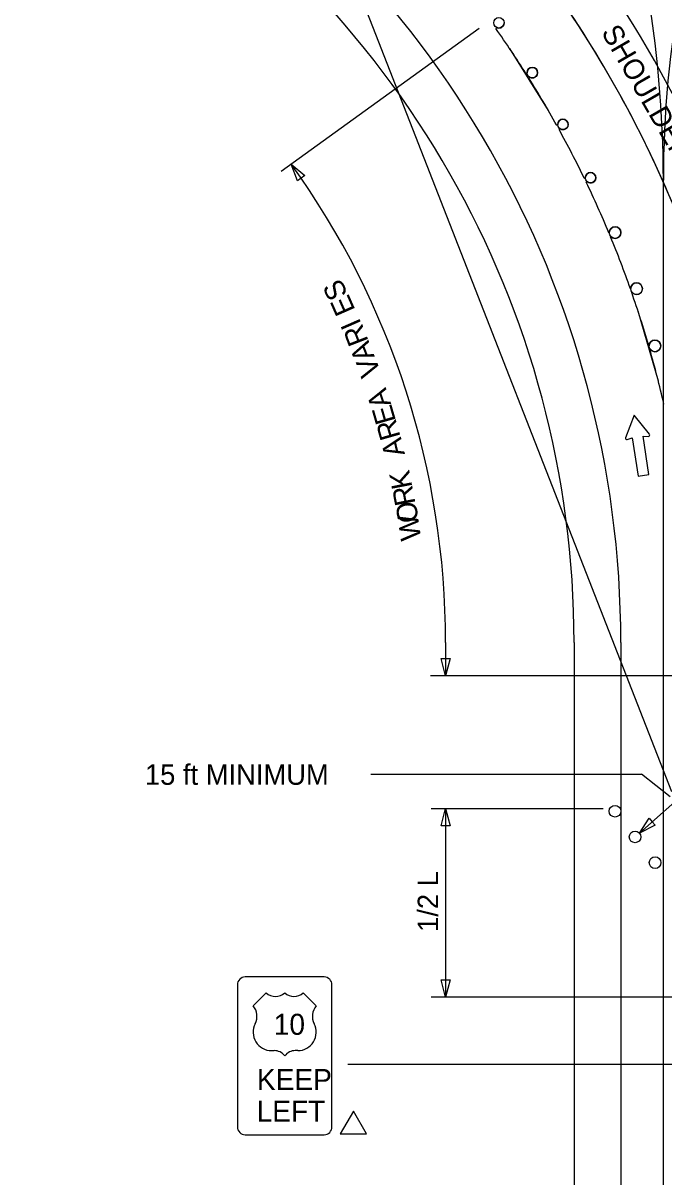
# Model space of a CAD drawing. Extents: x 16715 to 19504, y 7040 to 8495.
# Drawn here: x 16714.6 to 16934, y 7602.5 to 7997.5 of the extents above; entities that cross this region are included whole.
import ezdxf

# ---------------------------------------------------------------- set-up
doc = ezdxf.new("R2010")
doc.units = 0
for name, color, linetype in [('ALI_LEGAL_EX', 7, 'Continuous'), ('MT_SCRATCH_LEVEL_A', 7, 'Continuous'), ('MT_SCRATCH_LEVEL_E', 7, 'Continuous'), ('PAVT_EDGE_EX', 7, 'Continuous'), ('TRAFFIC_SIGNS_PR', 7, 'Continuous'), ('TYPICAL_EX', 7, 'Continuous'), ('TYPICAL_TEXT_DIMEN_PR', 7, 'Continuous')]:
    doc.layers.add(name, color=color, linetype=linetype)

msp = doc.modelspace()

# ---------------------------------------------------------------- linework, layer by layer
at = {"layer": 'ALI_LEGAL_EX'}
for p, q in [((16714.57, 8302.79), (16936.6, 7734.43)), ((16933.79, 7333.59), (16933.79, 7943.78)), ((16933.79, 7333.59), (16933.79, 7943.78))]:
    msp.add_line(p, q, dxfattribs=at)
for points in [[(16894.42, 7967.59), (16881.19, 7988.8)], [(16932.16, 7874.89), (16925.15, 7898.89)]]:
    msp.add_lwpolyline(points, dxfattribs=at)
for centre, radius, start, end in [((16545.79, 7943.78), 388, 0, 40.1908), ((17297.79, 7943.78), 364, 137.516, 180)]:
    msp.add_arc(centre, radius, start, end, dxfattribs=at)
at = {"layer": 'MT_SCRATCH_LEVEL_A'}
for points in [[(16876.9, 7995.96), (16876.46, 7995.65)], [(16886.74, 7980.31), (16887.14, 7980.57)], [(16888.15, 7978.95), (16887.75, 7978.69)], [(16897.24, 7962.65), (16897.61, 7962.86)], [(16898.45, 7961.34), (16898.08, 7961.14)], [(16906.72, 7944.43), (16907.06, 7944.6)], [(16907.74, 7943.19), (16907.4, 7943.03)], [(16915.14, 7925.77), (16915.28, 7925.83)], [(16915.87, 7924.42), (16915.72, 7924.36)], [(16922.52, 7906.58), (16922.63, 7906.62)], [(16923.06, 7905.38), (16922.96, 7905.34)], [(16928.81, 7887), (16928.89, 7887.03)], [(16929.2, 7885.97), (16929.12, 7885.94)]]:
    msp.add_lwpolyline(points, dxfattribs=at)
for centre, radius, start, end in [((16579.24, 7785.52), 388, 22.8554, 35.7873), ((16877.5, 7997.65), 1.8, 250.5205, 0), ((16579.24, 7785.52), 364, 32.3536, 35.2603), ((16888.94, 7980.56), 1.8, 0, 180), ((16888.94, 7980.56), 1.8, 244.1065, 0), ((16579.24, 7785.52), 364, 29.1198, 32.0533), ((16899.41, 7962.86), 1.8, 0, 180), ((16579.24, 7785.52), 364, 25.8855, 28.8467), ((16899.41, 7962.86), 1.8, 237.6934, 0), ((16908.86, 7944.6), 1.8, 0, 180), ((16579.24, 7785.52), 364, 22.663, 25.6406), ((16908.86, 7944.6), 1.8, 231.2811, 0), ((16917.28, 7925.83), 2, 0, 180), ((16917.28, 7925.83), 2, 224.8459, 0), ((16579.24, 7785.52), 364, 19.4261, 22.4229), ((16924.63, 7906.62), 2, 0, 180), ((16579.24, 7785.52), 364, 16.189, 19.219), ((16924.63, 7906.62), 2, 218.4379, 0), ((16930.89, 7887.03), 2, 0, 180), ((16579.24, 7785.52), 364, 12.9515, 16.0153), ((16930.89, 7887.03), 2, 212.0306, 0)]:
    msp.add_arc(centre, radius, start, end, dxfattribs=at)
at = {"layer": 'MT_SCRATCH_LEVEL_E'}
for p, q in [((16923.84, 7863.32), (16920.87, 7855.55)), ((16929.03, 7856.79), (16923.84, 7863.32)), ((16921.44, 7854.94), (16923.15, 7855.52)), ((16923.15, 7855.52), (16925.15, 7842.42)), ((16928.85, 7842.98), (16926.85, 7856.09)), ((16926.85, 7856.09), (16928.66, 7856.04)), ((16925.15, 7842.42), (16928.85, 7842.98))]:
    msp.add_line(p, q, dxfattribs=at)
for centre, start, end in [((16921.3, 7855.39), 159.1026, 288.6416), ((16928.66, 7856.51), 268.714, 38.4509)]:
    msp.add_arc(centre, 0.463, start, end, dxfattribs=at)
at = {"layer": 'PAVT_EDGE_EX'}
for p, q in [((16903.24, 7785.52), (16903.24, 7430.94)), ((16919.24, 7785.52), (16919.24, 7430.94))]:
    msp.add_line(p, q, dxfattribs=at)
for radius, start in [(404, 15.917), (388, 0), (340, 0), (324, 0)]:
    msp.add_arc((16579.24, 7785.52), radius, start, 59.3713, dxfattribs=at)
at = {"layer": 'TRAFFIC_SIGNS_PR'}
for p, q in [((16787.94, 7668.24), (16787.94, 7619.64)), ((16817.64, 7670.94), (16790.64, 7670.94)), ((16820.34, 7619.64), (16820.34, 7668.24)), ((16790.64, 7616.94), (16817.64, 7616.94))]:
    msp.add_line(p, q, dxfattribs=at)
for centre, radius in [((16877.5, 7997.65), 1.8), ((16888.94, 7980.56), 1.8), ((16899.41, 7962.86), 1.8), ((16908.86, 7944.6), 1.8), ((16917.28, 7925.83), 2), ((16924.63, 7906.62), 2), ((16930.89, 7887.03), 2), ((16917.24, 7727.68), 2), ((16924.1, 7718.89), 2), ((16930.96, 7710.09), 2)]:
    msp.add_circle(centre, radius, dxfattribs=at)
for centre, start, end in [((16790.64, 7668.24), 90, 180), ((16817.64, 7668.24), 0, 90), ((16790.64, 7619.64), 180, 270), ((16817.64, 7619.64), 270, 0)]:
    msp.add_arc(centre, 2.7, start, end, dxfattribs=at)
at = {"layer": 'TYPICAL_EX'}
for p, q in [((16793.34, 7661.04), (16797.84, 7665.54)), ((16814.95, 7661.04), (16810.44, 7665.54)), ((16799.64, 7645.73), (16800.54, 7645.73)), ((16808.65, 7645.73), (16807.75, 7645.73))]:
    msp.add_line(p, q, dxfattribs=at)
for centre, radius, start, end in [((16800.99, 7668.82), 4.55, 226.1404, 313.8596), ((16807.29, 7668.82), 4.55, 226.1404, 313.8596), ((16789.08, 7657.44), 5.58, 333.0977, 40.1936), ((16819.21, 7657.44), 5.58, 139.8064, 206.9023), ((16799.65, 7652.02), 6.29, 152.6698, 269.9013), ((16808.64, 7652.02), 6.29, 270.0987, 27.3302), ((16800.55, 7641.22), 4.51, 37.1038, 90.1385), ((16807.74, 7641.22), 4.51, 89.8615, 142.8962)]:
    msp.add_arc(centre, radius, start, end, dxfattribs=at)
at = {"layer": 'TYPICAL_TEXT_DIMEN_PR'}
for p, q in [((16870.73, 7995.65), (16802.94, 7946.78)), ((16808.52, 7943.57), (16806.36, 7949.24)), ((16806.36, 7949.24), (16811.07, 7945.41)), ((16811.07, 7945.41), (16809.79, 7944.49)), ((16809.79, 7944.49), (16808.52, 7943.57)), ((16859.24, 7785.52), (16859.24, 7774.07)), ((16859.24, 7774.07), (16857.67, 7779.93)), ((16857.67, 7779.93), (16859.24, 7779.93)), ((16859.24, 7779.93), (16860.81, 7779.93)), ((16860.81, 7779.93), (16859.24, 7774.07)), ((16939.53, 7774.07), (16854.01, 7774.07)), ((16833.68, 7740.44), (16926.29, 7740.44)), ((16925.6, 7720.21), (16949.25, 7741.14)), ((16936.15, 7732.63), (16926.29, 7740.44)), ((16854.24, 7728.58), (16913.15, 7728.58)), ((16857.67, 7722.72), (16859.24, 7728.58)), ((16859.24, 7728.58), (16859.24, 7664.07)), ((16859.24, 7728.58), (16860.81, 7722.72)), ((16925.6, 7720.21), (16928.95, 7725.28)), ((16928.95, 7725.28), (16929.99, 7724.1)), ((16929.99, 7724.1), (16931.03, 7722.92)), ((16859.24, 7722.72), (16857.67, 7722.72)), ((16860.81, 7722.72), (16859.24, 7722.72)), ((16931.03, 7722.92), (16925.6, 7720.21)), ((16859.24, 7664.07), (16857.67, 7669.93)), ((16857.67, 7669.93), (16859.24, 7669.93)), ((16859.24, 7669.93), (16860.81, 7669.93)), ((16860.81, 7669.93), (16859.24, 7664.07)), ((16958.13, 7664.07), (16854.24, 7664.07)), ((16825.81, 7641.12), (16946.75, 7641.12))]:
    msp.add_line(p, q, dxfattribs=at)
msp.add_lwpolyline([(16827.66, 7625.05), (16823.14, 7617.22), (16832.19, 7617.22)], close=True, dxfattribs=at)
msp.add_arc((16579.24, 7785.52), 280, 0, 35.7874, dxfattribs=at)

# ---------------------------------------------------------------- texts
at = {"layer": 'TRAFFIC_SIGNS_PR'}
for s, p in [('10', (16800.39, 7651.14)), ('KEEP', (16794.62, 7632.24)), ('LEFT', (16794.52, 7621.44))]:
    msp.add_text(s, height=7.2, dxfattribs=at).set_placement(p)
at = {"layer": 'TYPICAL_TEXT_DIMEN_PR'}
for s, rotation, p in [('SHOULDER', 300.0663, (16912.36, 7994.41)), ('S', 116.1586, (16825.93, 7904.81)), ('E', 113.6993, (16828.42, 7899.31)), ('I', 113.6993, (16830.48, 7894.61)), ('R', 111.1369, (16832.93, 7888.69)), ('A', 111.1369, (16835, 7883.35)), ('V', 108.5745, (16837.09, 7877.72)), ('A', 108.5745, (16840.66, 7867.08)), ('E', 106.0121, (16842.3, 7861.35)), ('R', 106.0121, (16843.86, 7855.93)), ('A', 103.4497, (16845.35, 7849.95)), ('K', 100.8873, (16847.88, 7838.68)), ('R', 100.8873, (16848.97, 7833.03)), ('O', 98.3249, (16850.03, 7826.95)), ('W', 98.3249, (16850.91, 7820.92)), ('1/2 L', 90, (16856.68, 7686.37))]:
    msp.add_text(s, height=7, rotation=rotation, dxfattribs=at).set_placement(p)
msp.add_text('15 ft MINIMUM', height=7, dxfattribs=at).set_placement((16756.29, 7736.74))

doc.saveas('drawing.dxf')
